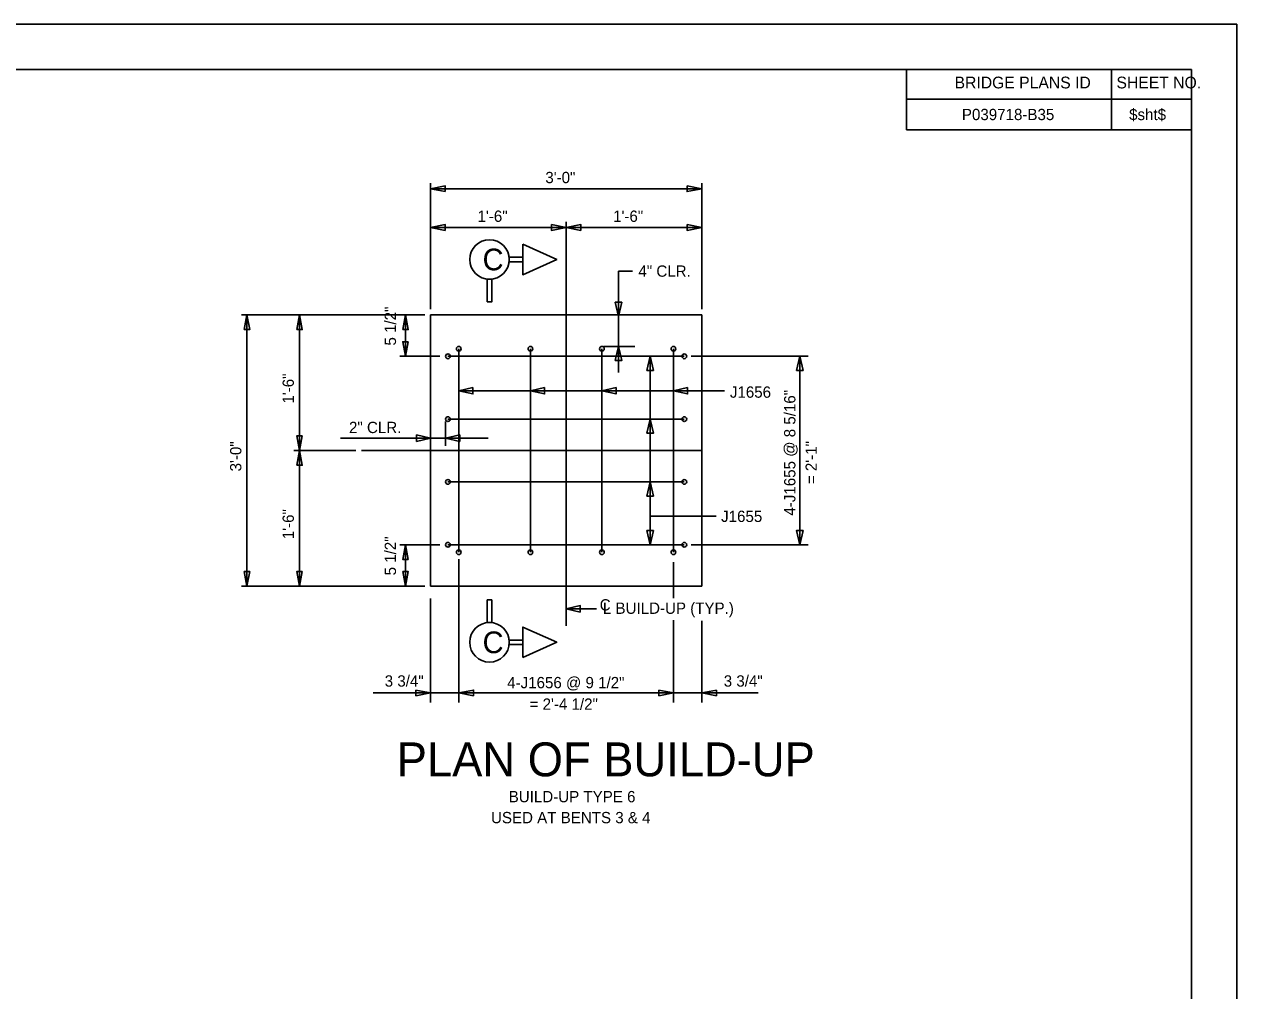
# Model space of a CAD drawing. Extents: x -133.1 to -97, y -110.1 to -88.1.
# Drawn here: x -110.56 to -97.14, y -98.79 to -88.1 of the extents above; entities that cross this region are included whole.
import ezdxf

# ---------------------------------------------------------------- set-up
doc = ezdxf.new("R2010")
doc.units = 0
for name, color, linetype in [('BR_AUTO DIMENSION', 7, 'Continuous'), ('BR_BORDER LINES', 7, 'Continuous'), ('BR_CENTER LINES', 7, 'Continuous'), ('BR_CONCRETE', 7, 'Continuous'), ('BR_REBAR', 7, 'Continuous'), ('BR_TEXT', 7, 'Continuous'), ('Level 31', 7, 'Continuous')]:
    doc.layers.add(name, color=color, linetype=linetype)

msp = doc.modelspace()

# ---------------------------------------------------------------- linework, layer by layer
at = {"layer": 'BR_AUTO DIMENSION'}
for p, q in [((-106.06, -91.255), (-106.06, -89.86)), ((-103.06, -91.255), (-103.06, -89.86)), ((-106.06, -89.922), (-103.06, -89.922)), ((-106.06, -90.35), (-104.56, -90.35)), ((-104.56, -91.255), (-104.56, -90.288)), ((-103.06, -90.35), (-104.56, -90.35)), ((-103.981, -91.954), (-103.981, -90.833)), ((-103.827, -90.833), (-103.981, -90.833)), ((-106.123, -91.317), (-108.154, -91.317)), ((-108.092, -94.317), (-108.092, -91.317)), ((-107.511, -91.317), (-107.511, -92.817)), ((-106.338, -91.317), (-106.338, -91.775)), ((-104.149, -91.666), (-103.8, -91.666)), ((-105.96, -91.775), (-106.4, -91.775)), ((-103.631, -91.775), (-103.631, -93.859)), ((-103.176, -91.775), (-101.884, -91.775)), ((-101.976, -91.775), (-101.976, -93.859)), ((-105.748, -92.155), (-102.808, -92.155)), ((-105.894, -92.496), (-105.894, -92.765)), ((-105.425, -92.681), (-107.059, -92.681)), ((-106.886, -92.817), (-107.573, -92.817)), ((-107.511, -94.317), (-107.511, -92.817)), ((-103.631, -93.542), (-102.902, -93.542)), ((-105.96, -93.859), (-106.4, -93.859)), ((-106.338, -94.317), (-106.338, -93.859)), ((-103.176, -93.859), (-101.884, -93.859)), ((-105.748, -94.018), (-105.748, -95.603)), ((-103.373, -94.05), (-103.373, -94.45)), ((-106.123, -94.317), (-108.154, -94.317)), ((-106.06, -94.452), (-106.06, -95.603)), ((-104.56, -94.568), (-104.224, -94.568)), ((-103.373, -94.693), (-103.373, -95.603)), ((-103.06, -94.701), (-103.06, -95.603)), ((-105.748, -95.497), (-106.696, -95.497)), ((-105.748, -95.497), (-103.373, -95.497)), ((-103.373, -95.497), (-103.312, -95.497)), ((-103.312, -95.497), (-102.436, -95.497))]:
    msp.add_line(p, q, dxfattribs=at)
for points in [[(-105.898, -89.954), (-106.06, -89.922), (-105.898, -89.891)], [(-103.223, -89.891), (-103.06, -89.922), (-103.223, -89.954)], [(-105.898, -90.382), (-106.06, -90.35), (-105.898, -90.319)], [(-104.723, -90.319), (-104.56, -90.35), (-104.723, -90.382)], [(-104.398, -90.382), (-104.56, -90.35), (-104.398, -90.319)], [(-103.223, -90.319), (-103.06, -90.35), (-103.223, -90.382)], [(-103.945, -91.177), (-103.981, -91.333), (-104.017, -91.177)], [(-108.123, -91.48), (-108.092, -91.317), (-108.061, -91.48)], [(-107.542, -91.48), (-107.511, -91.317), (-107.48, -91.48)], [(-106.369, -91.48), (-106.338, -91.317), (-106.307, -91.48)], [(-106.307, -91.613), (-106.338, -91.775), (-106.369, -91.613)], [(-104.017, -91.822), (-103.981, -91.666), (-103.945, -91.822)], [(-103.667, -91.931), (-103.631, -91.775), (-103.595, -91.931)], [(-102.012, -91.931), (-101.976, -91.775), (-101.94, -91.931)], [(-105.592, -92.119), (-105.748, -92.155), (-105.592, -92.191)], [(-104.8, -92.119), (-104.956, -92.155), (-104.8, -92.191)], [(-104.009, -92.119), (-104.165, -92.155), (-104.009, -92.191)], [(-103.217, -92.119), (-103.373, -92.155), (-103.217, -92.191)], [(-103.667, -92.626), (-103.631, -92.47), (-103.595, -92.626)], [(-107.48, -92.655), (-107.511, -92.817), (-107.542, -92.655)], [(-106.216, -92.717), (-106.06, -92.681), (-106.216, -92.645)], [(-105.738, -92.645), (-105.894, -92.681), (-105.738, -92.717)], [(-107.542, -92.98), (-107.511, -92.817), (-107.48, -92.98)], [(-103.667, -93.32), (-103.631, -93.164), (-103.595, -93.32)], [(-103.595, -93.703), (-103.631, -93.859), (-103.667, -93.703)], [(-101.94, -93.703), (-101.976, -93.859), (-102.012, -93.703)], [(-106.307, -94.021), (-106.338, -93.859), (-106.369, -94.021)], [(-108.061, -94.155), (-108.092, -94.317), (-108.123, -94.155)], [(-107.48, -94.155), (-107.511, -94.317), (-107.542, -94.155)], [(-106.369, -94.155), (-106.338, -94.317), (-106.307, -94.155)], [(-104.404, -94.604), (-104.56, -94.568), (-104.404, -94.532)], [(-106.223, -95.466), (-106.06, -95.497), (-106.223, -95.528)], [(-105.585, -95.528), (-105.748, -95.497), (-105.585, -95.466)], [(-103.535, -95.466), (-103.373, -95.497), (-103.535, -95.528)], [(-102.898, -95.466), (-103.06, -95.497), (-102.898, -95.528)]]:
    msp.add_lwpolyline(points, close=True, dxfattribs=at)
at = {"layer": 'BR_BORDER LINES'}
for p, q in [((-97.642, -88.603), (-131.308, -88.603)), ((-100.794, -89.269), (-100.794, -88.603)), ((-98.528, -89.269), (-98.528, -88.603)), ((-97.642, -109.603), (-97.642, -88.603)), ((-100.794, -88.932), (-97.642, -88.932)), ((-98.528, -88.932), (-97.642, -88.932)), ((-97.642, -89.269), (-100.794, -89.269))]:
    msp.add_line(p, q, dxfattribs=at)
at = {"layer": 'BR_CENTER LINES'}
for p, q in [((-104.56, -91.147), (-104.56, -94.756)), ((-103.06, -92.817), (-106.824, -92.817))]:
    msp.add_line(p, q, dxfattribs=at)
at = {"layer": 'BR_CONCRETE'}
for p, q in [((-106.06, -91.317), (-106.06, -94.317)), ((-106.06, -91.317), (-103.06, -91.317)), ((-103.06, -91.317), (-103.06, -94.317)), ((-103.06, -94.317), (-106.06, -94.317))]:
    msp.add_line(p, q, dxfattribs=at)
at = {"layer": 'BR_REBAR'}
for p, q in [((-105.748, -93.942), (-105.748, -91.692)), ((-104.956, -93.942), (-104.956, -91.692)), ((-104.165, -93.942), (-104.165, -91.692)), ((-103.373, -93.942), (-103.373, -91.692)), ((-105.868, -91.775), (-103.253, -91.775)), ((-105.868, -92.47), (-103.253, -92.47)), ((-105.868, -93.164), (-103.253, -93.164)), ((-105.868, -93.859), (-103.253, -93.859))]:
    msp.add_line(p, q, dxfattribs=at)
for centre in [(-105.868, -91.775), (-105.748, -91.692), (-104.956, -91.692), (-104.165, -91.692), (-103.373, -91.692), (-103.253, -91.775), (-105.868, -92.47), (-103.253, -92.47), (-105.868, -93.164), (-103.253, -93.164), (-105.868, -93.859), (-103.253, -93.859), (-105.748, -93.942), (-104.956, -93.942), (-104.165, -93.942), (-103.373, -93.942)]:
    msp.add_circle(centre, 0.026, dxfattribs=at)
at = {"layer": 'BR_TEXT'}
for points in [[(-105.04, -90.535), (-104.665, -90.704), (-105.04, -90.873)], [(-105.19, -90.729), (-105.04, -90.729), (-105.04, -90.679), (-105.19, -90.679)], [(-105.434, -91.173), (-105.384, -91.173), (-105.384, -90.923), (-105.434, -90.923)], [(-105.434, -94.469), (-105.384, -94.469), (-105.384, -94.719), (-105.434, -94.719)], [(-105.04, -95.107), (-104.665, -94.938), (-105.04, -94.769)], [(-105.19, -94.913), (-105.04, -94.913), (-105.04, -94.963), (-105.19, -94.963)]]:
    msp.add_lwpolyline(points, close=True, dxfattribs=at)
for centre in [(-105.409, -90.704), (-105.409, -94.938)]:
    msp.add_circle(centre, 0.219, dxfattribs=at)
at = {"layer": 'Level 31'}
msp.add_lwpolyline([(-133.141, -110.103), (-97.141, -110.103), (-97.141, -88.103), (-133.141, -88.103)], close=True, dxfattribs=at)

# ---------------------------------------------------------------- texts
at = {"layer": 'BR_AUTO DIMENSION'}
for s, p in [('3\'-0"', (-104.791, -89.86)), ('1\'-6"', (-105.541, -90.288)), ('1\'-6"', (-104.041, -90.288)), ('4" CLR.', (-103.761, -90.895)), ('J1656', (-102.749, -92.233)), ('2" CLR.', (-106.963, -92.624)), ('J1655', (-102.846, -93.607)), ('C', (-104.189, -94.586)), ('L BUILD-UP (TYP.)', (-104.154, -94.623)), ('3 3/4"', (-106.568, -95.428)), ('4-J1656 @ 9 1/2"', (-105.213, -95.446)), ('3 3/4"', (-102.817, -95.428)), ('= 2\'-4 1/2"', (-104.965, -95.684)), ('BUILD-UP TYPE 6', (-105.196, -96.707)), ('USED AT BENTS 3 & 4', (-105.392, -96.939))]:
    msp.add_text(s, height=0.125, dxfattribs=at).set_placement(p)
for s, p in [('5 1/2"', (-106.443, -91.656)), ('1\'-6"', (-107.573, -92.298)), ('4-J1655 @ 8 5/16"', (-102.024, -93.537)), ('3\'-0"', (-108.154, -93.048)), ('= 2\'-1"', (-101.787, -93.189)), ('1\'-6"', (-107.573, -93.798)), ('5 1/2"', (-106.443, -94.198))]:
    msp.add_text(s, height=0.125, rotation=90, dxfattribs=at).set_placement(p)
at = {"layer": 'BR_TEXT'}
for s, height, p in [('BRIDGE PLANS ID', 0.13, (-100.263, -88.812)), ('SHEET NO.', 0.13, (-98.472, -88.812)), ('P039718-B35', 0.125, (-100.182, -89.163)), ('$sht$', 0.125, (-98.332, -89.163)), ('C', 0.24, (-105.485, -90.824)), ('C', 0.24, (-105.485, -95.058)), ('PLAN OF BUILD-UP', 0.375, (-106.435, -96.42))]:
    msp.add_text(s, height=height, dxfattribs=at).set_placement(p)

doc.saveas('drawing.dxf')
